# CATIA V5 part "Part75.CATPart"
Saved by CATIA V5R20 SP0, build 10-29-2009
Part number: IA 3075SF
Revision: ANY
Definition: UNKNOWN
Nomenclature: IA 3075SF
Source: Unknown
Bounding box of the stored display mesh (mm): x -1.5 to 1.5, y -2.85 to 4.9, z -1.5 to 1.5
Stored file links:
  C:\Users\Utente\Desktop\IO LAVORO\3D X SITO CF\CUMSA\3D files FA\FA 053004-20\Part75.CATPart

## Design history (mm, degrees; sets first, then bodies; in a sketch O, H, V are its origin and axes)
Body1 "Cortar-Extruir1" (main body)
  Solid1: solid without history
